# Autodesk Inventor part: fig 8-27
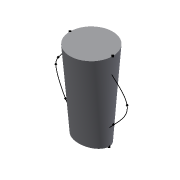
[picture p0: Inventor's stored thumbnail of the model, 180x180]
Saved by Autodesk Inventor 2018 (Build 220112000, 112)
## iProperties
Shininess: 64.0
Length Units: 11269
Angle Units: 11279
Time Units: 11290
Mass Units: 11283
Length Display Precision: 3
Angle Display Precision: 2
Compacted: True
Part Number: fig 8-27
Document SubType Name: Modeling
Created: 2002-12
Designer: deepak
Density: 1 g/cm^3
Material: Generic
Appearance: Default
Density: 0.0
Volumn: 0.0
Area: 0.0
PropertySet Name: Model Information
Control State: 0
Master: False
Checked Out: False
Author: deepak
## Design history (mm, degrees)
sketch "Sketch1"
  geometry: 2 further points; 1 other entity
  constraints: 1 coincident, 3 other
workplane "Work Plane1"
workplane "Work Plane2"
sketch "Sketch3"
  geometry: C1 r 60 at (0, 0); 1 further point
  constraints: 1 centre point, 1 coincident, 1 other
sketch "Sketch4"
  geometry: 8 further points
  constraints: 8 other
sketch "Sketch5"
  geometry: 6 further points
  constraints: 6 other
sketch "Sketch6"
  geometry: 6 further points
  constraints: 6 other
  dimensions: "d20" = 35 distance of point (0, 0) point (-35, 0); "d21" = 0 vertical distance of point (0, 0) point (-35, 0); "d22" = 225 vertical distance of point (0, 0) point (-60, 225); "d23" = 60 horizontal distance of point (0, 0) point (-60, 225); "d24" = 100 horizontal distance of point (0, 0) point (-100, 125); "d25" = 125 vertical distance of point (0, 0) point (-100, 125)
loft "Loft4" dims "d50" = 0, "d51" = 90 deg, "d52" = 0, "d53" = 90 deg
body "Solid1"
other parameters: "d5" = 125
